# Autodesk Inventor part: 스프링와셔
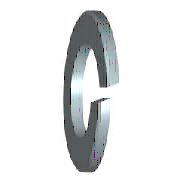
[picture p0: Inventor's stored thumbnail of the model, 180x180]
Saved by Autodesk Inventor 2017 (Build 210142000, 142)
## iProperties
IsCustomPart: 1
Created: 2012-02
Part Number: 스프링와셔
Material: 강철, 연강
Description: 스프링 와셔
Document SubType Name: Modeling
Standard: JIS B 1251
Designer: mduedu
Standards Organization: JIS
Language: ko-KR
Size Designation: 번호 2 4
Categories: <MemberInstance><Categories><Category DisplayName="조임쇠" InternalName="e4da775c-781d-43d5-af7c-5136215cf5a6" Mnemonic="FSTN"><Category DisplayName="와셔" InternalN
Density: 7.85 g/cm^3
Appearance: 노란색
Mass: 0.246957 g
Surface Area: 1.02615 cm^2
Volume: 0.0314594 cm^3
Author: mduedu
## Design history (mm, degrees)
sketch "스케치1"
  geometry: C1 r 3.8 at (0, 0); C2 r 2.05 at (0, 0); 1 further point
  constraints: 2 centre point, 2 coincident
  dimensions: "d0" = 4.1 diameter of C2 (= SD1); "d1" = 7.6 diameter of C1 (= SD2)
extrude "본체" new body sketch "스케치1" distance "d2" = 1 (= SD); taper "d3" = 0 deg
sketch "스케치2"
  geometry: L1 (0, -2.05)-(0, 2.05) reference; L2 (1, 3.8)-(1, -3.8) reference; L3 (-1.2, 0)-(7.2, 0) reference; L4 (0, -0.2)-(1, 0.164); L5 (0, 0.2)-(1, 0.564)
  constraints: 4 end point, 4 point on line, 1 parallel
  dimensions: "d4" = 0.2 distance from line of L3 L4.start (= 0.2 x SD); "d5" = 0.2 distance from line of L3 L5.start (= 0.2 x SD); "d6" = 70 deg angle of L2 L4 (= FAWI)
extrude "절단부" cut sketch "스케치2" stored distance "d7" = 1 (= SD); taper "d8" = 0 deg
workaxis "Work Axis1"
workplane "Work Plane1"
body "Solid1"
other parameters: "SD1" = 4.1 [user parameter; used in 1 equation term], "SD2" = 7.6 [user parameter; used in 1 equation term], "SD" = 1 [user parameter; used in 4 equation terms], "FAWI" = 70 deg [user parameter; used in 1 equation term], "d9" = 0, "d10" = 0, "d11" = 0, "d12" = 0, "SDI" = 1.4 [user parameter], "NND" = 4 [user parameter]
